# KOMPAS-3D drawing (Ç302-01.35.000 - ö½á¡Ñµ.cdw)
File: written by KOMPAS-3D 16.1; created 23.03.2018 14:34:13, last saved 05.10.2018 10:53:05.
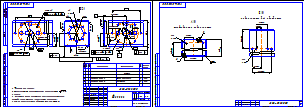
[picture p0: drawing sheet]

Sheets 1-2: A3, landscape

Title block, sheet 1: name: Фланец; designation: А302-01.35.000; mass: 4,25; scale: 1:2; sheet number: 1; sheets: 2; organisation: ЗАО «Астерион»; sheet format: A3; stored path: \\192.168.87.28\Konstructor_doc\Мембранные насосы\Мембранный электропривод\А302-00.00.000 - ASTRA-302 (МЭ200)\Чертежи\А302-00.35.000 - Фланец.cdw; drawn by: Милов; technical control: Лучихин
Title block, sheet 2: sheet number: 2; stored path: Z:\Мембранные насосы\Мембранный электропривод\А302-00.00.000 - ASTRA-302 (МЭ200)\3Д ПВХ\А302-01.35.000 - Фланец.cdw

Views: Вид 1, Спереди, Проекционный вид 2, Местный разрез 1, Проекционный вид 3, Вид по стрелке 4, Вид по стрелке 5
Referenced files in Z:\Мембранные насосы\Мембранный электропривод\А302-00.00.000 - ASTRA-302 (МЭ200)\3Д\: А302-00.35.000 - Фланец.a3d, А302-00.35.001 - Труба 140х140х4.m3d, А302-00.35.002 - Пластина.m3d
Referenced files in \\192.168.87.28\Konstructor_doc\Мембранные насосы\Мембранный электропривод\А302-00.00.000 - ASTRA-302 (МЭ200)\3Д ПВХ\: А302-01.35.000 - Фланец.a3d
Referenced files in \\192.168.87.28\Konstructor_doc\Мембранные насосы\Мембранный электропривод\А302-00.00.000 - ASTRA-302 (МЭ200)\3Д\: А302-00.35.001 - Труба 140х140х4.m3d, А302-00.35.002 - Пластина.m3d
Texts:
  Ra 2,5
  шлифованная поверхность
  поверхность без обработки
  *Размеры для справок.
  Шероховатость дорабатываемых поверхностей  Ra 3,2 .
  Сварка.
  Покрытие: Эмаль порошковая эпоксидно-полиэфирная,
  цвет RAL5005, шагрень (допускается глянцевая).
  Общие допуски ГОСТ 30893.2-mK (H14, h14,  t2/2).
  Пластина
  Труба 140х140х4
Dimensions and other numbers on the sheet: 80; 72±0,1; 139; 0,03; 0,05; 95; 9; 8 отв.; 69,5±0,05; 160; 130; 6 отв.; 34; 3 отв.; 20; 175,8±0,1; 139,5; 14,5; 20,5; 10,25; -6Н/0,5 45; 4; 21; 269; 249±0,3; 8,8; 2 отв.; 100±0,2; 1; 2; 50±0,1; 108±0,2; 31,5±0,1; 63±0,2; 4 отв.; 106±0,2; 53±0,1; 1:2; 4,25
